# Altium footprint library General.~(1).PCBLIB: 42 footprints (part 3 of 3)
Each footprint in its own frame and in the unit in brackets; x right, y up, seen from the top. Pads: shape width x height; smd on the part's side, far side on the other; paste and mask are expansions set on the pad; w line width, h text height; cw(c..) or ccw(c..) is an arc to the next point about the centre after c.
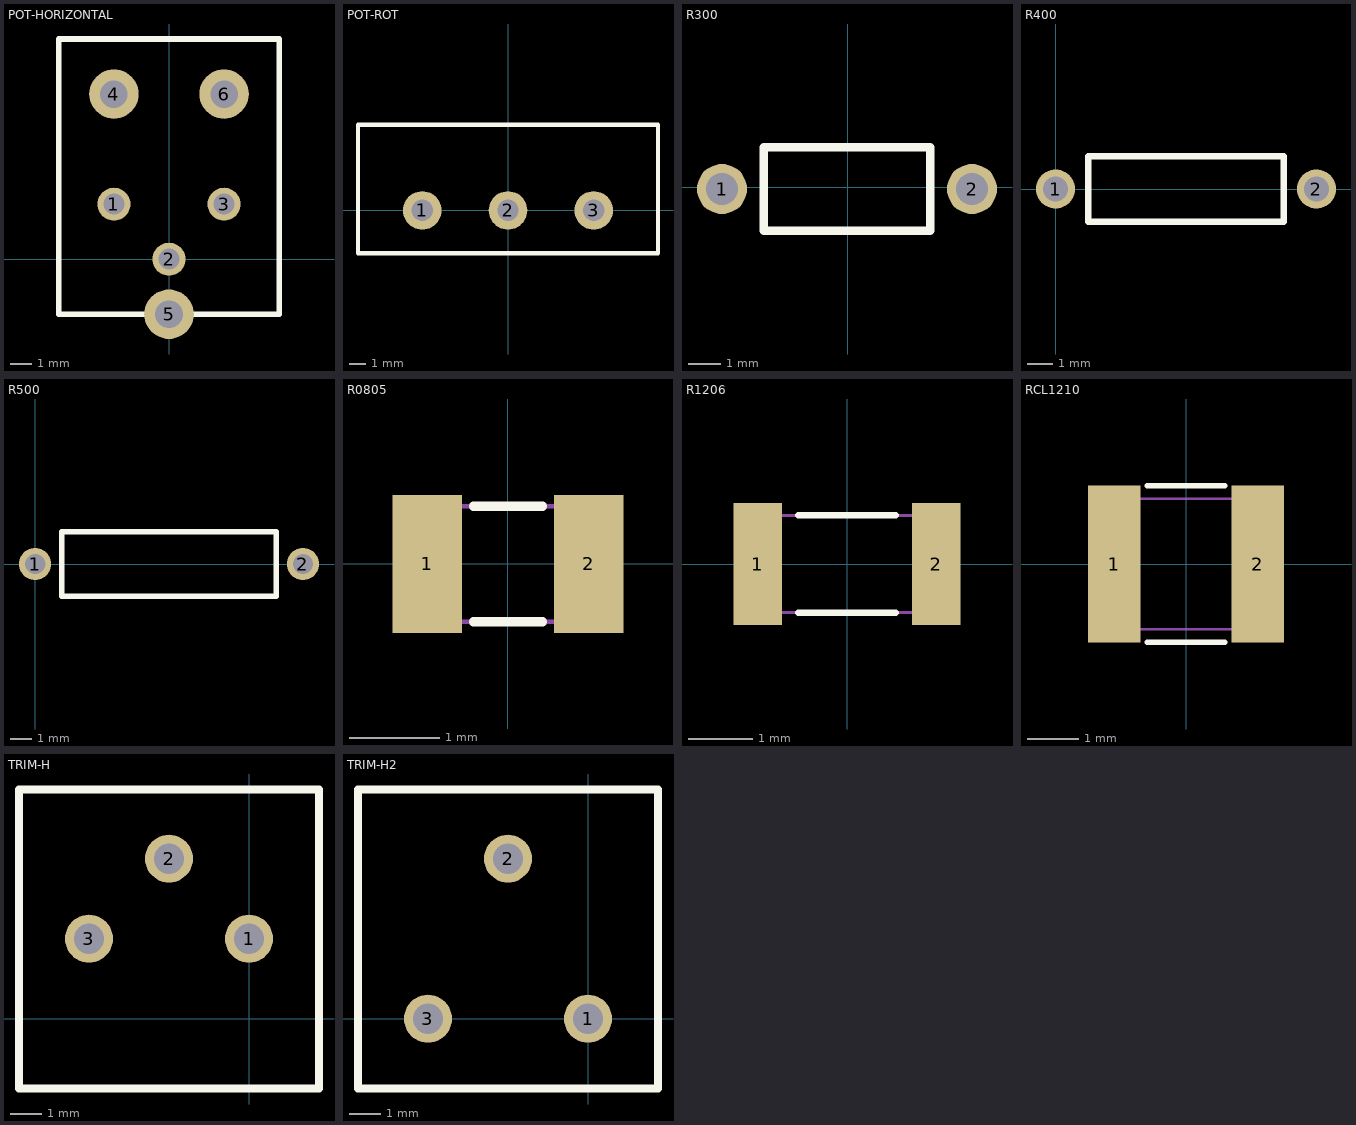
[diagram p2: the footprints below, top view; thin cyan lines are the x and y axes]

## POT-HORIZONTAL [mil]
pads (6):
  round 60 hole 38: 1(-100,100) 2(0,0) 3(100,100)
  round 90 hole 50: 4(-100,300) 5(0,-100) 6(100,300)
Top Overlay:
  lines w10: -200,-100 200,-100 200,400 -200,400 -200,-100

## POT-ROT [mil]
pads (3):
  round 90 hole 50: 1(-200,0) 2(0,0) 3(200,0)
Top Overlay:
  lines w10: -350,-100 350,-100 350,200 -350,200 -350,-100
3D body "User Library-Pot.step": height 789.95, standoff -179.4, extent -310,-810.22 310,196

## R300 [mil]
pads (2):
  round 60 hole 38: 1(-151,-2) 2(149,-2)
Top Overlay:
  lines w10: -101,-52 99,-52 99,48 -101,48 -101,-52
3D body "User Library-Resistencia-1.step": height 76.53, standoff -61.76, extent -161,-40.48 159,36

## R400 [mil]
pads (2):
  round 60 hole 38: 1(0,0) 2(400,0)
Top Overlay:
  lines w10: 50,-50 50,50 350,50 350,-50 50,-50
3D body "User Library-RESISTOR, 0_25 W, 0_4 IN LEAD PITCH.step": height 91, standoff -124.5, extent -12,-45 412,46

## R500 [mil]
pads (2):
  round 60 hole 38: 1(0,0) 2(500,0)
Top Overlay:
  lines w10: 50,-60 50,60 450,60 450,-60 50,-60
3D body "User Library-res_05x12_5.STEP": height 125.98, standoff -86.61, extent -8,-62.99 507.75,62.99

## R0805 [mil]
pads (2):
  rect 30x60 smd: 1(-35,0) 2(35,0)
Top Overlay:
  lines w4: -15,-25 15,-25 ; -15,25 15,25
Mechanical 1:
  lines w1.97: -40,-25 -40,25 ; 40,-25 40,25
  lines w2: -40,-25 40,-25 ; -40,25 40,25
3D body "User Library-0805 SMD Resistor.step": height 31.39, standoff 0.6, extent -39.37,-25 39.37,24.21

## R1206 [mil]
pads (2):
  rect 30x75 smd: 1(-55,0) 2(55,0)
Top Overlay:
  lines w4: -30,-30 30,-30 ; -30,30 30,30
Mechanical 1:
  lines w1.97: -60,-30 60,-30 60,30 -60,30 -60,-30
3D body "User Library-1206 SMD Resistor.step": height 40.05, standoff 0.6, extent -62.99,-31.99 62.99,31

## RCL1210 [mil]
pads (2):
  rect 40x120 smd: 1(-55,0) 2(55,0)
Top Overlay:
  lines w4: -30,-60 30,-60 ; -30,60 30,60
Mechanical 1:
  lines w1.97: -65,-50 65,-50 65,50 -65,50 -65,-50

## TRIM-H [mil]
pads (3):
  round 60 hole 38: 1(0,100) 2(-100,200) 3(-200,100)
Top Overlay:
  lines w10: -287.4,-87.4 -287.4,286.61 87.4,286.61 87.4,-87.4 -287.4,-87.4
3D body "SW3DPS-CERMET TRIMMER SINGLE TURN 10MM 500MW TOP ADJUST-DEFAULT.step": height 190.76, standoff -196.25, extent -287.6,-90 87.6,285.2

## TRIM-H2 [mil]
pads (3):
  round 60 hole 38: 1(0,0) 2(-100,200) 3(-200,0)
Top Overlay:
  lines w10: -287.4,-87.4 -287.4,286.61 87.4,286.61 87.4,-87.4 -287.4,-87.4
3D body "SW3DPS-CERMET TRIMMER SINGLE TURN 10MM 500MW TOP ADJUST-DEFAULT.step": height 190.76, standoff -196.25, extent -290.2,-87.6 85,287.6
